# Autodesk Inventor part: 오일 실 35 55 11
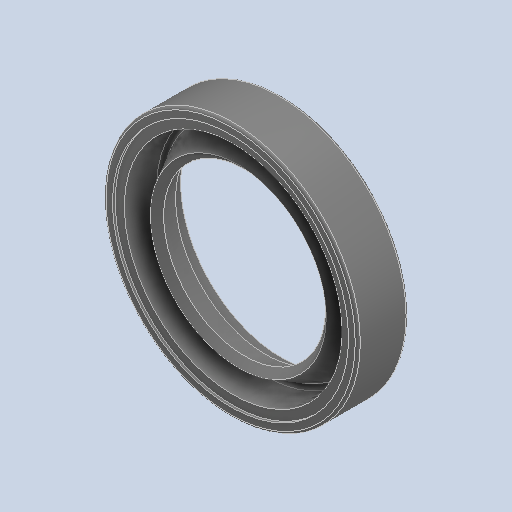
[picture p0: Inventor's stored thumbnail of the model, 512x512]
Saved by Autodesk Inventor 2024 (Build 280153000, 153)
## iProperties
Created: 2025-05
Part Number: 오일 실 35 55 11
Material: 고무
Description: 오일 실 - 비스프링, 조립 GA
Document SubType Name: Modeling
Designer: 11
Density: 0.93 g/cm^3
Appearance: 기본값
Author: jhkim
Sending System: Autodesk Inventor 2026
Preprocessor: ST-DEVELOPER v20.1
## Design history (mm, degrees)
node "오일 실 35 55 111"
node "솔리드1"
body "Solid1"
